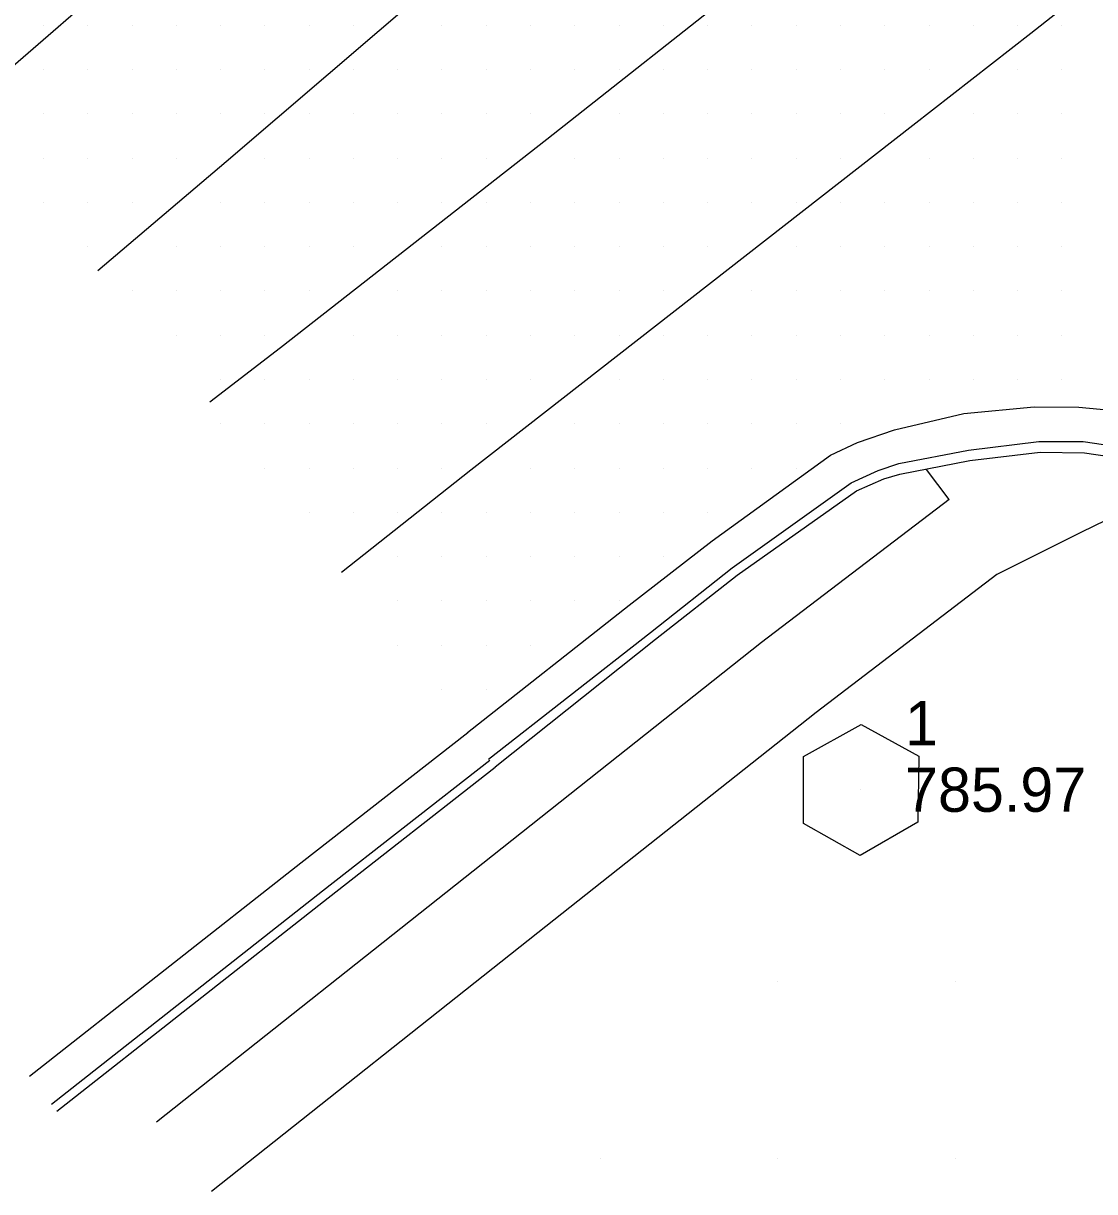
# Model space of a CAD drawing. Extents: x 1762120 to 1766775, y 709485 to 712965.
# Drawn here: x 1765762.6 to 1765823.1, y 709542.9 to 709608.9 of the extents above; entities that cross this region are included whole.
import ezdxf

# ---------------------------------------------------------------- set-up
doc = ezdxf.new("R2010")
doc.units = 0
for name, color, linetype in [('CTL Primary Horizontal and Vertical CELL', 7, 'Continuous'), ('CTL Primary Horizontal and Vertical Cogo Elevation', 7, 'Continuous'), ('CTL Primary Horizontal and Vertical Cogo Number', 7, 'Continuous'), ('Exist DTM Drainline', 7, 'Continuous'), ('Exist DTM QL2 LIDAR Elevation Point', 7, 'Continuous'), ('Exist DTM Scan Elevation Point', 7, 'Continuous'), ('Exist Roads Curbs', 7, 'Continuous'), ('Exist Roads EOP', 7, 'Continuous'), ('Exist Roads EOT', 7, 'Continuous'), ('PH Exist DTM Breakline', 7, 'Continuous')]:
    doc.layers.add(name, color=color, linetype=linetype)

msp = doc.modelspace()

# ---------------------------------------------------------------- linework, layer by layer
at = {"layer": 'CTL Primary Horizontal and Vertical CELL'}
msp.add_line((1765809.899, 709565.596), (1765809.899, 709565.596), dxfattribs=at)
msp.add_lwpolyline([(1765806.668, 709567.468), (1765809.918, 709569.28), (1765813.168, 709567.493), (1765813.118, 709563.768), (1765809.868, 709561.88), (1765806.668, 709563.693)], close=True, dxfattribs=at)
at = {"layer": 'Exist DTM Drainline'}
msp.add_lwpolyline([(1765788.876, 709567.324), (1765798.02, 709574.478), (1765802.632, 709578.114), (1765809.348, 709582.926), (1765810.88, 709583.615), (1765812.047, 709584.006), (1765815.981, 709584.754), (1765819.946, 709585.257), (1765822.456, 709585.244), (1765824.107, 709584.999), (1765828.023, 709584.173), (1765830.513, 709583.293), (1765834.03, 709581.389), (1765837.405, 709579.209), (1765838.742, 709578.097)], dxfattribs=at)
at = {"layer": 'Exist DTM QL2 LIDAR Elevation Point'}
for p, q in [((1765805.218, 709554.774), (1765805.218, 709554.774)), ((1765815.219, 709554.774), (1765815.219, 709554.774)), ((1765795.216, 709544.773), (1765795.216, 709544.773)), ((1765805.218, 709544.773), (1765805.218, 709544.773)), ((1765815.219, 709544.773), (1765815.219, 709544.773))]:
    msp.add_line(p, q, dxfattribs=at)
at = {"layer": 'Exist DTM Scan Elevation Point'}
for p, q in [((1765763.75, 709608.75), (1765763.75, 709608.75)), ((1765766.25, 709608.75), (1765766.25, 709608.75)), ((1765768.75, 709608.75), (1765768.75, 709608.75)), ((1765771.25, 709608.75), (1765771.25, 709608.75)), ((1765773.75, 709608.75), (1765773.75, 709608.75)), ((1765776.25, 709608.75), (1765776.25, 709608.75)), ((1765778.75, 709608.75), (1765778.75, 709608.75)), ((1765781.25, 709608.75), (1765781.25, 709608.75)), ((1765786.25, 709608.75), (1765786.25, 709608.75)), ((1765788.75, 709608.75), (1765788.75, 709608.75)), ((1765791.25, 709608.75), (1765791.25, 709608.75)), ((1765793.75, 709608.75), (1765793.75, 709608.75)), ((1765796.25, 709608.75), (1765796.25, 709608.75)), ((1765798.75, 709608.75), (1765798.75, 709608.75)), ((1765801.25, 709608.75), (1765801.25, 709608.75)), ((1765803.75, 709608.75), (1765803.75, 709608.75)), ((1765806.25, 709608.75), (1765806.25, 709608.75)), ((1765808.75, 709608.75), (1765808.75, 709608.75)), ((1765811.25, 709608.75), (1765811.25, 709608.75)), ((1765813.75, 709608.75), (1765813.75, 709608.75)), ((1765816.25, 709608.75), (1765816.25, 709608.75)), ((1765818.75, 709608.75), (1765818.75, 709608.75)), ((1765821.25, 709608.75), (1765821.25, 709608.75)), ((1765763.75, 709606.25), (1765763.75, 709606.25)), ((1765766.25, 709606.25), (1765766.25, 709606.25)), ((1765768.75, 709606.25), (1765768.75, 709606.25)), ((1765771.25, 709606.25), (1765771.25, 709606.25)), ((1765773.75, 709606.25), (1765773.75, 709606.25)), ((1765776.25, 709606.25), (1765776.25, 709606.25)), ((1765778.75, 709606.25), (1765778.75, 709606.25)), ((1765781.25, 709606.25), (1765781.25, 709606.25)), ((1765783.75, 709606.25), (1765783.75, 709606.25)), ((1765786.25, 709606.25), (1765786.25, 709606.25)), ((1765788.75, 709606.25), (1765788.75, 709606.25)), ((1765791.25, 709606.25), (1765791.25, 709606.25)), ((1765793.75, 709606.25), (1765793.75, 709606.25)), ((1765796.25, 709606.25), (1765796.25, 709606.25)), ((1765798.75, 709606.25), (1765798.75, 709606.25)), ((1765801.25, 709606.25), (1765801.25, 709606.25)), ((1765803.75, 709606.25), (1765803.75, 709606.25)), ((1765806.25, 709606.25), (1765806.25, 709606.25)), ((1765808.75, 709606.25), (1765808.75, 709606.25)), ((1765811.25, 709606.25), (1765811.25, 709606.25)), ((1765813.75, 709606.25), (1765813.75, 709606.25)), ((1765818.75, 709606.25), (1765818.75, 709606.25)), ((1765821.25, 709606.25), (1765821.25, 709606.25)), ((1765763.75, 709603.75), (1765763.75, 709603.75)), ((1765766.25, 709603.75), (1765766.25, 709603.75)), ((1765768.75, 709603.75), (1765768.75, 709603.75)), ((1765771.25, 709603.75), (1765771.25, 709603.75)), ((1765773.75, 709603.75), (1765773.75, 709603.75)), ((1765776.25, 709603.75), (1765776.25, 709603.75)), ((1765778.75, 709603.75), (1765778.75, 709603.75)), ((1765781.25, 709603.75), (1765781.25, 709603.75)), ((1765783.75, 709603.75), (1765783.75, 709603.75)), ((1765786.25, 709603.75), (1765786.25, 709603.75)), ((1765788.75, 709603.75), (1765788.75, 709603.75)), ((1765791.25, 709603.75), (1765791.25, 709603.75)), ((1765796.25, 709603.75), (1765796.25, 709603.75)), ((1765798.75, 709603.75), (1765798.75, 709603.75)), ((1765801.25, 709603.75), (1765801.25, 709603.75)), ((1765803.75, 709603.75), (1765803.75, 709603.75)), ((1765806.25, 709603.75), (1765806.25, 709603.75)), ((1765808.75, 709603.75), (1765808.75, 709603.75)), ((1765811.25, 709603.75), (1765811.25, 709603.75)), ((1765816.25, 709603.75), (1765816.25, 709603.75)), ((1765818.75, 709603.75), (1765818.75, 709603.75)), ((1765821.25, 709603.75), (1765821.25, 709603.75)), ((1765763.75, 709601.25), (1765763.75, 709601.25)), ((1765766.25, 709601.25), (1765766.25, 709601.25)), ((1765768.75, 709601.25), (1765768.75, 709601.25)), ((1765771.25, 709601.25), (1765771.25, 709601.25)), ((1765776.25, 709601.25), (1765776.25, 709601.25)), ((1765778.75, 709601.25), (1765778.75, 709601.25)), ((1765781.25, 709601.25), (1765781.25, 709601.25)), ((1765783.75, 709601.25), (1765783.75, 709601.25)), ((1765786.25, 709601.25), (1765786.25, 709601.25)), ((1765788.75, 709601.25), (1765788.75, 709601.25)), ((1765793.75, 709601.25), (1765793.75, 709601.25)), ((1765796.25, 709601.25), (1765796.25, 709601.25)), ((1765798.75, 709601.25), (1765798.75, 709601.25)), ((1765801.25, 709601.25), (1765801.25, 709601.25)), ((1765803.75, 709601.25), (1765803.75, 709601.25)), ((1765806.25, 709601.25), (1765806.25, 709601.25)), ((1765808.75, 709601.25), (1765808.75, 709601.25)), ((1765813.75, 709601.25), (1765813.75, 709601.25)), ((1765816.25, 709601.25), (1765816.25, 709601.25)), ((1765818.75, 709601.25), (1765818.75, 709601.25)), ((1765821.25, 709601.25), (1765821.25, 709601.25)), ((1765763.75, 709598.75), (1765763.75, 709598.75)), ((1765766.25, 709598.75), (1765766.25, 709598.75)), ((1765768.75, 709598.75), (1765768.75, 709598.75)), ((1765773.75, 709598.75), (1765773.75, 709598.75)), ((1765776.25, 709598.75), (1765776.25, 709598.75)), ((1765778.75, 709598.75), (1765778.75, 709598.75)), ((1765781.25, 709598.75), (1765781.25, 709598.75)), ((1765783.75, 709598.75), (1765783.75, 709598.75)), ((1765786.25, 709598.75), (1765786.25, 709598.75)), ((1765788.75, 709598.75), (1765788.75, 709598.75)), ((1765791.25, 709598.75), (1765791.25, 709598.75)), ((1765793.75, 709598.75), (1765793.75, 709598.75)), ((1765796.25, 709598.75), (1765796.25, 709598.75)), ((1765798.75, 709598.75), (1765798.75, 709598.75)), ((1765801.25, 709598.75), (1765801.25, 709598.75)), ((1765803.75, 709598.75), (1765803.75, 709598.75)), ((1765806.25, 709598.75), (1765806.25, 709598.75)), ((1765808.75, 709598.75), (1765808.75, 709598.75)), ((1765811.25, 709598.75), (1765811.25, 709598.75)), ((1765813.75, 709598.75), (1765813.75, 709598.75)), ((1765816.25, 709598.75), (1765816.25, 709598.75)), ((1765818.75, 709598.75), (1765818.75, 709598.75)), ((1765821.25, 709598.75), (1765821.25, 709598.75)), ((1765766.25, 709596.25), (1765766.25, 709596.25)), ((1765771.25, 709596.25), (1765771.25, 709596.25)), ((1765773.75, 709596.25), (1765773.75, 709596.25)), ((1765776.25, 709596.25), (1765776.25, 709596.25)), ((1765778.75, 709596.25), (1765778.75, 709596.25)), ((1765781.25, 709596.25), (1765781.25, 709596.25)), ((1765786.25, 709596.25), (1765786.25, 709596.25)), ((1765788.75, 709596.25), (1765788.75, 709596.25)), ((1765791.25, 709596.25), (1765791.25, 709596.25)), ((1765793.75, 709596.25), (1765793.75, 709596.25)), ((1765796.25, 709596.25), (1765796.25, 709596.25)), ((1765798.75, 709596.25), (1765798.75, 709596.25)), ((1765801.25, 709596.25), (1765801.25, 709596.25)), ((1765806.25, 709596.25), (1765806.25, 709596.25)), ((1765808.75, 709596.25), (1765808.75, 709596.25)), ((1765811.25, 709596.25), (1765811.25, 709596.25)), ((1765813.75, 709596.25), (1765813.75, 709596.25)), ((1765816.25, 709596.25), (1765816.25, 709596.25)), ((1765818.75, 709596.25), (1765818.75, 709596.25)), ((1765821.25, 709596.25), (1765821.25, 709596.25)), ((1765768.75, 709593.75), (1765768.75, 709593.75)), ((1765771.25, 709593.75), (1765771.25, 709593.75)), ((1765773.75, 709593.75), (1765773.75, 709593.75)), ((1765776.25, 709593.75), (1765776.25, 709593.75)), ((1765778.75, 709593.75), (1765778.75, 709593.75)), ((1765783.75, 709593.75), (1765783.75, 709593.75)), ((1765786.25, 709593.75), (1765786.25, 709593.75)), ((1765788.75, 709593.75), (1765788.75, 709593.75)), ((1765791.25, 709593.75), (1765791.25, 709593.75)), ((1765793.75, 709593.75), (1765793.75, 709593.75)), ((1765796.25, 709593.75), (1765796.25, 709593.75)), ((1765798.75, 709593.75), (1765798.75, 709593.75)), ((1765803.75, 709593.75), (1765803.75, 709593.75)), ((1765806.25, 709593.75), (1765806.25, 709593.75)), ((1765808.75, 709593.75), (1765808.75, 709593.75)), ((1765811.25, 709593.75), (1765811.25, 709593.75)), ((1765813.75, 709593.75), (1765813.75, 709593.75)), ((1765816.25, 709593.75), (1765816.25, 709593.75)), ((1765818.75, 709593.75), (1765818.75, 709593.75)), ((1765821.25, 709593.75), (1765821.25, 709593.75)), ((1765771.25, 709591.25), (1765771.25, 709591.25)), ((1765773.75, 709591.25), (1765773.75, 709591.25)), ((1765776.25, 709591.25), (1765776.25, 709591.25)), ((1765781.25, 709591.25), (1765781.25, 709591.25)), ((1765783.75, 709591.25), (1765783.75, 709591.25)), ((1765786.25, 709591.25), (1765786.25, 709591.25)), ((1765788.75, 709591.25), (1765788.75, 709591.25)), ((1765791.25, 709591.25), (1765791.25, 709591.25)), ((1765793.75, 709591.25), (1765793.75, 709591.25)), ((1765796.25, 709591.25), (1765796.25, 709591.25)), ((1765798.75, 709591.25), (1765798.75, 709591.25)), ((1765801.25, 709591.25), (1765801.25, 709591.25)), ((1765803.75, 709591.25), (1765803.75, 709591.25)), ((1765806.25, 709591.25), (1765806.25, 709591.25)), ((1765808.75, 709591.25), (1765808.75, 709591.25)), ((1765811.25, 709591.25), (1765811.25, 709591.25)), ((1765813.75, 709591.25), (1765813.75, 709591.25)), ((1765816.25, 709591.25), (1765816.25, 709591.25)), ((1765818.75, 709591.25), (1765818.75, 709591.25)), ((1765821.25, 709591.25), (1765821.25, 709591.25)), ((1765773.75, 709588.75), (1765773.75, 709588.75)), ((1765776.25, 709588.75), (1765776.25, 709588.75)), ((1765778.75, 709588.75), (1765778.75, 709588.75)), ((1765781.25, 709588.75), (1765781.25, 709588.75)), ((1765783.75, 709588.75), (1765783.75, 709588.75)), ((1765786.25, 709588.75), (1765786.25, 709588.75)), ((1765788.75, 709588.75), (1765788.75, 709588.75)), ((1765791.25, 709588.75), (1765791.25, 709588.75)), ((1765796.25, 709588.75), (1765796.25, 709588.75)), ((1765798.75, 709588.75), (1765798.75, 709588.75)), ((1765801.25, 709588.75), (1765801.25, 709588.75)), ((1765803.75, 709588.75), (1765803.75, 709588.75)), ((1765806.25, 709588.75), (1765806.25, 709588.75)), ((1765808.75, 709588.75), (1765808.75, 709588.75)), ((1765811.25, 709588.75), (1765811.25, 709588.75)), ((1765813.75, 709588.75), (1765813.75, 709588.75)), ((1765816.25, 709588.75), (1765816.25, 709588.75)), ((1765818.75, 709588.75), (1765818.75, 709588.75)), ((1765821.25, 709588.75), (1765821.25, 709588.75)), ((1765773.75, 709586.25), (1765773.75, 709586.25)), ((1765776.25, 709586.25), (1765776.25, 709586.25)), ((1765778.75, 709586.25), (1765778.75, 709586.25)), ((1765781.25, 709586.25), (1765781.25, 709586.25)), ((1765783.75, 709586.25), (1765783.75, 709586.25)), ((1765786.25, 709586.25), (1765786.25, 709586.25)), ((1765788.75, 709586.25), (1765788.75, 709586.25)), ((1765793.75, 709586.25), (1765793.75, 709586.25)), ((1765796.25, 709586.25), (1765796.25, 709586.25)), ((1765798.75, 709586.25), (1765798.75, 709586.25)), ((1765801.25, 709586.25), (1765801.25, 709586.25)), ((1765803.75, 709586.25), (1765803.75, 709586.25)), ((1765806.25, 709586.25), (1765806.25, 709586.25)), ((1765808.75, 709586.25), (1765808.75, 709586.25)), ((1765776.25, 709583.75), (1765776.25, 709583.75)), ((1765778.75, 709583.75), (1765778.75, 709583.75)), ((1765781.25, 709583.75), (1765781.25, 709583.75)), ((1765783.75, 709583.75), (1765783.75, 709583.75)), ((1765786.25, 709583.75), (1765786.25, 709583.75)), ((1765791.25, 709583.75), (1765791.25, 709583.75)), ((1765793.75, 709583.75), (1765793.75, 709583.75)), ((1765796.25, 709583.75), (1765796.25, 709583.75)), ((1765798.75, 709583.75), (1765798.75, 709583.75)), ((1765801.25, 709583.75), (1765801.25, 709583.75)), ((1765803.75, 709583.75), (1765803.75, 709583.75)), ((1765806.25, 709583.75), (1765806.25, 709583.75)), ((1765778.75, 709581.25), (1765778.75, 709581.25)), ((1765781.25, 709581.25), (1765781.25, 709581.25)), ((1765783.75, 709581.25), (1765783.75, 709581.25)), ((1765786.25, 709581.25), (1765786.25, 709581.25)), ((1765788.75, 709581.25), (1765788.75, 709581.25)), ((1765791.25, 709581.25), (1765791.25, 709581.25)), ((1765793.75, 709581.25), (1765793.75, 709581.25)), ((1765796.25, 709581.25), (1765796.25, 709581.25)), ((1765798.75, 709581.25), (1765798.75, 709581.25)), ((1765801.25, 709581.25), (1765801.25, 709581.25)), ((1765783.75, 709578.75), (1765783.75, 709578.75)), ((1765786.25, 709578.75), (1765786.25, 709578.75)), ((1765788.75, 709578.75), (1765788.75, 709578.75)), ((1765791.25, 709578.75), (1765791.25, 709578.75)), ((1765793.75, 709578.75), (1765793.75, 709578.75)), ((1765796.25, 709578.75), (1765796.25, 709578.75)), ((1765798.75, 709578.75), (1765798.75, 709578.75)), ((1765783.75, 709576.25), (1765783.75, 709576.25)), ((1765786.25, 709576.25), (1765786.25, 709576.25)), ((1765788.75, 709576.25), (1765788.75, 709576.25)), ((1765791.25, 709576.25), (1765791.25, 709576.25)), ((1765793.75, 709576.25), (1765793.75, 709576.25)), ((1765796.25, 709576.25), (1765796.25, 709576.25)), ((1765783.75, 709573.75), (1765783.75, 709573.75)), ((1765786.25, 709573.75), (1765786.25, 709573.75)), ((1765788.75, 709573.75), (1765788.75, 709573.75)), ((1765791.25, 709573.75), (1765791.25, 709573.75)), ((1765786.25, 709571.25), (1765786.25, 709571.25)), ((1765788.75, 709571.25), (1765788.75, 709571.25))]:
    msp.add_line(p, q, dxfattribs=at)
at = {"layer": 'Exist Roads Curbs'}
msp.add_lwpolyline([(1765789.244, 709566.888), (1765798.299, 709574.097), (1765802.919, 709577.701), (1765809.661, 709582.473), (1765811.204, 709583.151), (1765812.111, 709583.412), (1765816.048, 709584.181), (1765820.024, 709584.642), (1765822.534, 709584.615), (1765823.943, 709584.4), (1765827.849, 709583.557), (1765830.176, 709582.674), (1765833.684, 709580.753), (1765837.047, 709578.55), (1765838.189, 709577.656)], dxfattribs=at)
at = {"layer": 'Exist Roads EOP'}
msp.add_lwpolyline([(1765787.699, 709568.829), (1765796.821, 709576.007), (1765801.498, 709579.647), (1765808.197, 709584.479), (1765809.705, 709585.202), (1765811.798, 709585.912), (1765815.709, 709586.836), (1765819.69, 709587.215), (1765822.202, 709587.193), (1765824.617, 709586.957), (1765828.551, 709586.194), (1765831.458, 709585.105), (1765835.002, 709583.252), (1765838.334, 709580.993), (1765840.511, 709579.47)], dxfattribs=at)
at = {"layer": 'Exist Roads EOT'}
for points in [[(1765773.149, 709587.484), (1765777.128, 709590.561), (1765792.168, 709602.316), (1765803.673, 709611.402), (1765815.39, 709620.449), (1765827.377, 709629.884), (1765839.177, 709639.283), (1765850.559, 709648.395), (1765862.184, 709658.073)], [(1765780.576, 709577.883), (1765787.885, 709583.651), (1765812.839, 709603.112), (1765819.496, 709608.311), (1765843.042, 709626.842), (1765850.171, 709632.674), (1765873.163, 709651.388)], [(1765759.047, 709603.873), (1765766.698, 709610.516), (1765782.765, 709624.477), (1765799.946, 709639.486)], [(1765766.826, 709594.912), (1765774.057, 709601.067), (1765791.342, 709615.862), (1765805.54, 709628.189), (1765807.813, 709630.17), (1765808.693, 709631.438)]]:
    msp.add_lwpolyline(points, dxfattribs=at)
at = {"layer": 'PH Exist DTM Breakline'}
msp.add_line((1765814.886, 709581.982), (1765813.608, 709583.675), dxfattribs=at)
for points in [[(1765828.667, 709583.208), (1765822.331, 709580.111), (1765817.575, 709577.744)], [(1765814.886, 709581.982), (1765804.301, 709573.901), (1765788.561, 709561.424), (1765770.138, 709546.823)], [(1765817.575, 709577.744), (1765807.372, 709569.955), (1765791.666, 709557.506), (1765773.243, 709542.904)], [(1765762.957, 709549.421), (1765778.278, 709561.463), (1765787.705, 709568.822)], [(1765764.192, 709547.849), (1765779.512, 709559.888), (1765788.951, 709567.257)], [(1765764.501, 709547.455), (1765779.82, 709559.495), (1765789.258, 709566.862)]]:
    msp.add_lwpolyline(points, dxfattribs=at)

# ---------------------------------------------------------------- texts
at = {"layer": 'CTL Primary Horizontal and Vertical Cogo Elevation'}
msp.add_text('785.97', height=2.5, dxfattribs=at).set_placement((1765812.399, 709564.346))
at = {"layer": 'CTL Primary Horizontal and Vertical Cogo Number'}
msp.add_text('1', height=2.5, dxfattribs=at).set_placement((1765812.399, 709568.096))

doc.saveas('drawing.dxf')
